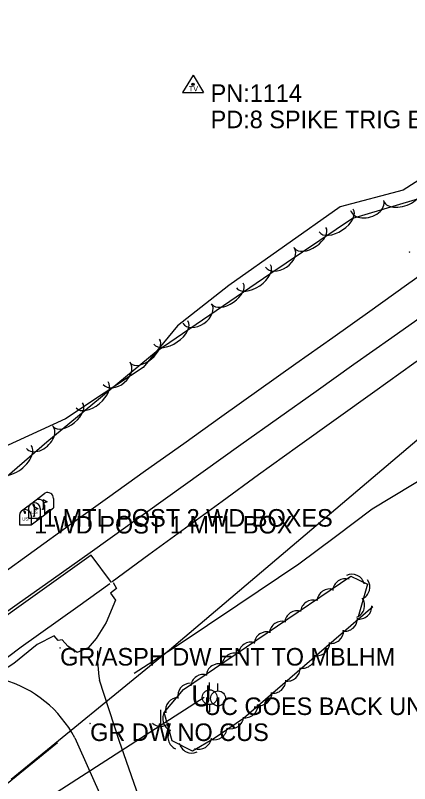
# Model space of a CAD drawing. Extents: x 1451369 to 1458940, y 1868647 to 1875095.
# Drawn here: x 1454030.9 to 1454143.2, y 1871239.9 to 1871458.6 of the extents above; entities that cross this region are included whole.
import ezdxf

# ---------------------------------------------------------------- set-up
doc = ezdxf.new("R2010")
doc.units = 0
for name, color, linetype in [('Default', 7, 'Continuous'), ('E_Const Align', 7, 'Continuous'), ('E_No Plot', 7, 'Continuous'), ('E_Proposed ROW and Easements', 7, 'Continuous'), ('E_Proposed ROW Fig Annot', 7, 'Continuous'), ('E_Quarter Section Line', 7, 'Continuous'), ('E_ROW Point Number', 7, 'Continuous'), ('E_Station Offset', 7, 'Continuous'), ('E_Survey Point Number', 7, 'Continuous'), ('S_EDGE_PAVEMENT', 7, 'Continuous'), ('S_EXIST_ROW', 7, 'Continuous'), ('S_MAILBOX_ANNOT', 7, 'Continuous'), ('S_PARKING', 7, 'Continuous'), ('S_PAVEMENT_CROWN', 7, 'Continuous'), ('S_SECONDARY_CTL_ANNOT', 7, 'Continuous'), ('S_SURVEY_TEXT_ANNOT', 7, 'Continuous'), ('S_UNDERGROUND_CABLE_ANNOT', 7, 'Continuous')]:
    doc.layers.add(name, color=color, linetype=linetype)

msp = doc.modelspace()

# ---------------------------------------------------------------- linework, layer by layer
at = {"layer": 'E_Const Align'}
for p, q in [((1454086.22, 1871266.55), (1454086.22, 1871268.68)), ((1454088.52, 1871266.28), (1454088.52, 1871268.39)), ((1454086.22, 1871262.33), (1454086.22, 1871260.27)), ((1454072.23, 1871260.88), (1454072.23, 1871256.16))]:
    msp.add_line(p, q, dxfattribs=at)
for centre, radius in [((1454086.24, 1871264.47), 2.11), ((1454088.64, 1871264.14), 2.13)]:
    msp.add_circle(centre, radius, dxfattribs=at)
msp.add_arc((1454072.29, 1871259.58), 3.41, 226.3972, 313.6028, dxfattribs=at)
at = {"layer": 'E_No Plot'}
msp.add_lwpolyline([(1454074.79, 1871277.88), (1454074.79, 1871277.93), (1454074.79, 1871277.88), (1454074.74, 1871277.88), (1454074.79, 1871277.88), (1454074.79, 1871277.83), (1454074.79, 1871277.88), (1454074.84, 1871277.88)], dxfattribs=at)
at = {"layer": 'E_Proposed ROW and Easements'}
for points in [[(1454143.12, 1871391.19), (1454143.12, 1871391.24), (1454143.12, 1871391.19), (1454143.07, 1871391.19), (1454143.12, 1871391.19), (1454143.12, 1871391.14), (1454143.12, 1871391.19), (1454143.17, 1871391.19)], [(1454043.64, 1871278.49), (1454043.64, 1871278.54), (1454043.64, 1871278.49), (1454043.59, 1871278.49), (1454043.64, 1871278.49), (1454043.64, 1871278.44), (1454043.64, 1871278.49), (1454043.69, 1871278.49)], [(1454052.19, 1871257.01), (1454052.19, 1871257.06), (1454052.19, 1871257.01), (1454052.14, 1871257.01), (1454052.19, 1871257.01), (1454052.19, 1871256.96), (1454052.19, 1871257.01), (1454052.24, 1871257.01)]]:
    msp.add_lwpolyline(points, dxfattribs=at)
at = {"layer": 'E_Proposed ROW Fig Annot'}
for p, q in [((1454035.18, 1871319.47), (1454039.32, 1871322.58)), ((1454041.75, 1871321.1), (1454041.75, 1871318.39)), ((1454032.62, 1871317.51), (1454036.76, 1871320.62)), ((1454036.24, 1871318.8), (1454036.24, 1871316.09)), ((1454038.8, 1871320.76), (1454038.8, 1871318.04)), ((1454039.19, 1871319.15), (1454039.19, 1871316.43)), ((1454034.63, 1871318.19), (1454034.63, 1871315.48)), ((1454037.96, 1871315.48), (1454041.75, 1871318.39)), ((1454037.96, 1871318.19), (1454037.96, 1871315.48)), ((1454032.07, 1871316.24), (1454032.07, 1871313.52)), ((1454034.63, 1871315.48), (1454037.96, 1871315.48)), ((1454035.39, 1871313.52), (1454039.19, 1871316.43)), ((1454035.39, 1871316.24), (1454035.39, 1871313.52)), ((1454032.07, 1871313.52), (1454035.39, 1871313.52))]:
    msp.add_line(p, q, dxfattribs=at)
for points in [[(1454035.82, 1871319.31), (1454036.04, 1871319.17), (1454036.04, 1871318.78), (1454036.34, 1871318.78), (1454036.34, 1871319.14), (1454036.15, 1871319.39), (1454035.82, 1871319.34)], [(1454036.24, 1871318.8), (1454037.35, 1871318.14), (1454036.24, 1871317.79)], [(1454038.8, 1871320.76), (1454039.91, 1871320.09), (1454038.8, 1871319.75)], [(1454033.25, 1871317.35), (1454033.47, 1871317.22), (1454033.47, 1871316.83), (1454033.78, 1871316.83), (1454033.78, 1871317.19), (1454033.59, 1871317.44), (1454033.25, 1871317.38)]]:
    msp.add_lwpolyline(points, dxfattribs=at)
for centre, end in [((1454040.09, 1871321.1), 117.5718), ((1454036.29, 1871318.19), 180), ((1454037.53, 1871319.15), 117.5718), ((1454033.73, 1871316.24), 180)]:
    msp.add_arc(centre, 1.66, 0, end, dxfattribs=at)
for centre in [(1454038.8, 1871318.04), (1454036.24, 1871316.09)]:
    msp.add_ellipse(centre, major_axis=(0.145, 0.132), ratio=0.564646, dxfattribs=at)
at = {"layer": 'E_Quarter Section Line'}
for p, q in [((1454214.32, 1871396.25), (1454074.79, 1871277.88)), ((1454074.79, 1871277.88), (1454029.66, 1871241.04))]:
    msp.add_line(p, q, dxfattribs=at)
at = {"layer": 'E_ROW Point Number'}
for points in [[(1454225.87, 1871461.79), (1454192.81, 1871439.12), (1454167.71, 1871418.57), (1454152.7, 1871408.42), (1454126.89, 1871400.74), (1454103.34, 1871384.91), (1454070.96, 1871362.85), (1454039.82, 1871337.12), (1453992.45, 1871296.2)], [(1454132.67, 1871290.19), (1454095.85, 1871258.38), (1454087.55, 1871252.77), (1454081.39, 1871249.11), (1454075.55, 1871252.05), (1454073.28, 1871260.08), (1454078.77, 1871266.7), (1454126.42, 1871298.91), (1454131.19, 1871296.67), (1454128.55, 1871287.33)]]:
    msp.add_lwpolyline(points, dxfattribs=at)
for centre, major_axis, ratio, start_param, end_param in [((1454141.03, 1871407.16), (5.11, 1.52), 0.542113, 3.141907, 6.2835), ((1454131.11, 1871404.48), (4.74, 1.41), 0.687103, 3.142126, 6.283719), ((1454122.28, 1871400.2), (4.87, 3.27), 0.550075, 3.141593, 6.283185), ((1454114.92, 1871395.25), (4.44, 2.98), 0.540695, 3.141593, 6.283185), ((1454106.22, 1871389.72), (4.11, 2.76), 0.685305, 3.141593, 6.283185), ((1454098.69, 1871384.31), (4.85, 3.3), 0.550075, 3.141593, 6.283185), ((1454091.36, 1871379.32), (4.42, 3.01), 0.540695, 3.141593, 6.283185), ((1454082.7, 1871373.73), (4.1, 2.79), 0.685305, 3.141593, 6.283185), ((1454075.19, 1871368.3), (4.85, 3.3), 0.550075, 3.141593, 6.283185), ((1454067.83, 1871363.02), (4.12, 3.41), 0.540696, 3.141593, 6.283185), ((1454059.73, 1871356.66), (3.82, 3.16), 0.685306, 3.141593, 6.283185), ((1454052.76, 1871350.56), (4.52, 3.74), 0.550076, 3.141593, 6.283185), ((1454045.92, 1871344.91), (4.12, 3.41), 0.540696, 3.141593, 6.283185), ((1454037.78, 1871338.51), (3.75, 3.24), 0.685331, 3.141629, 6.283222), ((1454030.95, 1871332.26), (4.44, 3.84), 0.550096, 3.141615, 6.283208), ((1454126.74, 1871295.83), (-3.3, 1.55), 0.999916, 3.825789, 5.598989), ((1454124.9, 1871294.58), (-1.86, -3.13), 0.999975, 3.385404, 5.158604), ((1454128.23, 1871295.83), (-3.32, 1.49), 0.993074, 2.400516, 4.173717), ((1454120.44, 1871291.66), (-1.86, -3.13), 0.999975, 3.385404, 5.158604), ((1454126.75, 1871290.63), (-3.32, 1.49), 0.993074, 2.400516, 4.173717), ((1454115.75, 1871288.52), (-1.86, -3.13), 0.999975, 3.385404, 5.158605), ((1454128.79, 1871290.36), (-1.23, 3.43), 0.999719, 2.624497, 4.397697), ((1454111.24, 1871285.48), (-1.86, -3.13), 0.999975, 3.385404, 5.158605), ((1454106.86, 1871282.47), (-1.86, -3.13), 0.999975, 3.385404, 5.158604), ((1454124.71, 1871286.92), (-1.23, 3.43), 0.999719, 2.624497, 4.397697), ((1454102.53, 1871279.46), (-1.86, -3.13), 0.999975, 3.385404, 5.158604), ((1454120.76, 1871283.42), (-1.23, 3.43), 0.999719, 2.624497, 4.397697), ((1454098.07, 1871276.53), (-1.86, -3.13), 0.999975, 3.385404, 5.158604), ((1454116.77, 1871279.92), (-1.23, 3.43), 0.999719, 2.624497, 4.397697), ((1454093.37, 1871273.39), (-1.86, -3.13), 0.999975, 3.385404, 5.158605), ((1454112.65, 1871276.37), (-1.23, 3.43), 0.999719, 2.624497, 4.397697), ((1454088.86, 1871270.35), (-1.86, -3.13), 0.999975, 3.385404, 5.158605), ((1454084.49, 1871267.35), (-1.86, -3.13), 0.999975, 3.385404, 5.158604), ((1454108.36, 1871272.7), (-1.23, 3.43), 0.999719, 2.624497, 4.397697), ((1454104.28, 1871269.27), (-1.23, 3.43), 0.999719, 2.624497, 4.397697), ((1454080.76, 1871264.81), (2.49, -2.66), 0.995904, 2.381358, 4.154559), ((1454077.31, 1871260.76), (2.49, -2.66), 0.995904, 2.381358, 4.154559), ((1454100.33, 1871265.76), (-1.23, 3.43), 0.999719, 2.624497, 4.397697), ((1454096.34, 1871262.27), (-1.23, 3.43), 0.999719, 2.624497, 4.397697), ((1454076.5, 1871258.36), (-0.4, -3.62), 0.999768, 4.212067, 5.985268), ((1454092.28, 1871259.14), (3.02, 2.04), 0.99998, 3.825789, 5.598989), ((1454087.59, 1871256.01), (3.02, 2.04), 0.99998, 3.825789, 5.598989), ((1454077.98, 1871253.12), (-0.4, -3.62), 0.999768, 4.212067, 5.985268), ((1454081.15, 1871252.21), (2.54, -2.61), 0.9999, 4.157531, 5.930732), ((1454083.15, 1871253.34), (-0.9, 3.53), 0.999827, 2.541953, 4.315153)]:
    msp.add_ellipse(centre, major_axis=major_axis, ratio=ratio, start_param=start_param, end_param=end_param, dxfattribs=at)
at = {"layer": 'E_Station Offset'}
for p, q in [((1454081.5, 1871441.59), (1454078.49, 1871436.63)), ((1454081.5, 1871441.59), (1454084.45, 1871436.63)), ((1454078.49, 1871436.63), (1454084.45, 1871436.63))]:
    msp.add_line(p, q, dxfattribs=at)
for radius in [0.311, 0.183, 0.103]:
    msp.add_circle((1454081.5, 1871438.98), radius, dxfattribs=at)
at = {"layer": 'E_Survey Point Number'}
msp.add_line((1454084.63, 1871264.41), (1454036.46, 1871233.42), dxfattribs=at)
at = {"layer": 'S_EDGE_PAVEMENT'}
for points in [[(1454173.72, 1871404.14), (1454163.25, 1871396.68), (1454152.79, 1871389.23), (1454142.32, 1871381.77), (1454131.86, 1871374.32), (1454121.32, 1871366.84), (1454110.78, 1871359.35), (1454100.24, 1871351.87), (1454089.7, 1871344.39), (1454078.83, 1871336.64), (1454067.96, 1871328.89), (1454057.09, 1871321.14), (1454046.23, 1871313.39), (1454026.17, 1871298.9), (1454006.11, 1871284.4), (1453989.42, 1871272.42), (1453978.82, 1871264.94), (1453968.21, 1871257.46), (1453957.61, 1871249.98), (1453947.01, 1871242.51), (1453929.87, 1871230.39)], [(1454185.01, 1871388.14), (1454177.7, 1871382.57), (1454160.58, 1871370.75), (1454144.37, 1871359.47), (1454133.32, 1871351.56), (1454122.27, 1871343.65), (1454111.22, 1871335.74), (1454100.17, 1871327.83), (1454089.75, 1871320.21), (1454079.33, 1871312.59), (1454068.91, 1871304.97), (1454058.49, 1871297.35)], [(1454058.27, 1871297.14), (1454052.51, 1871304.9), (1454032.56, 1871290.65), (1454020.68, 1871282.23), (1454008.81, 1871273.8), (1454000.36, 1871267.57), (1453995.51, 1871263.87), (1453998.91, 1871258.87), (1454001.34, 1871255.84), (1454014.47, 1871265.24), (1454032.57, 1871278.79), (1454048.7, 1871290.33), (1454057.83, 1871296.85)], [(1454058.72, 1871297.11), (1454059.72, 1871295.46), (1454057.98, 1871294.09), (1454059.4, 1871292.13), (1454056.72, 1871285.74), (1454053.94, 1871281.16), (1454051.62, 1871278.54), (1454048.45, 1871277.23), (1454045.82, 1871279.05), (1454044.18, 1871280.81), (1454043.08, 1871280.66), (1454041.95, 1871282), (1454037.07, 1871279.5), (1454030.44, 1871274.03), (1454025.53, 1871270.97), (1454020.65, 1871267.99), (1454016.09, 1871265.75)]]:
    msp.add_lwpolyline(points, dxfattribs=at)
at = {"layer": 'S_EXIST_ROW'}
for points in [[(1454165.41, 1871421.39), (1454158.98, 1871420.15), (1454141.36, 1871408.85), (1454123.38, 1871404.07), (1454107.55, 1871392.87), (1454091.72, 1871381.67), (1454077.11, 1871370.25), (1454067.26, 1871358.33), (1454056.22, 1871351.03), (1454045.19, 1871343.73), (1454027.6, 1871335.62)], [(1454064.7, 1871271.29), (1454076.94, 1871279.19), (1454094.28, 1871290.8), (1454111.61, 1871302.41), (1454122.07, 1871310.24), (1454132.53, 1871318.08), (1454149.99, 1871328.61), (1454167.45, 1871339.14), (1454179.62, 1871344.24)], [(1454042.87, 1871251.45), (1454027.01, 1871238.63)]]:
    msp.add_lwpolyline(points, dxfattribs=at)
at = {"layer": 'S_PARKING'}
for points in [[(1454106.8, 1871068), (1454094.84, 1871117.33), (1454089.1, 1871154.74), (1454083.76, 1871181.06), (1454071.7, 1871220.04), (1454060.42, 1871252.14), (1454054.87, 1871269.35)], [(1454047.83, 1871252.9), (1454059.9, 1871225.83)]]:
    msp.add_lwpolyline(points, dxfattribs=at)
for centre, major_axis, ratio, start_param, end_param in [((1454091.76, 1871277.55), (-17.48, -34.67), 0.956561, 5.159484, 5.376742), ((1454018.86, 1871237.67), (-17.15, 28.44), 0.985488, 4.654519, 5.470219)]:
    msp.add_ellipse(centre, major_axis=major_axis, ratio=ratio, start_param=start_param, end_param=end_param, dxfattribs=at)
at = {"layer": 'S_PAVEMENT_CROWN'}
msp.add_lwpolyline([(1454179.61, 1871396.18), (1454169.23, 1871388.84), (1454158.84, 1871381.49), (1454148.46, 1871374.14), (1454138.08, 1871366.8), (1454127.34, 1871359.17), (1454116.6, 1871351.55), (1454105.86, 1871343.93), (1454095.11, 1871336.3), (1454084.38, 1871328.63), (1454073.65, 1871320.95), (1454062.91, 1871313.27), (1454052.18, 1871305.6), (1454041.79, 1871298.22), (1454031.39, 1871290.85), (1454021, 1871283.47), (1454010.6, 1871276.1), (1453994.45, 1871264.5), (1453984.08, 1871257.16), (1453973.71, 1871249.81), (1453963.34, 1871242.47), (1453952.97, 1871235.12), (1453935.67, 1871223.29)], dxfattribs=at)

# ---------------------------------------------------------------- texts
at = {"layer": 'Default'}
msp.add_text('U', height=6, rotation=360, dxfattribs=at).set_placement((1454081, 1871261.87))
at = {"layer": 'E_Proposed ROW Fig Annot'}
for p in [(1454035.39, 1871316.67), (1454032.83, 1871314.72)]:
    msp.add_text('US', height=0.96, rotation=360, dxfattribs=at).set_placement(p)
at = {"layer": 'E_Station Offset'}
msp.add_text('TV', height=1.5, rotation=360, dxfattribs=at).set_placement((1454080.3, 1871436.97))
at = {"layer": 'S_MAILBOX_ANNOT'}
for s, p in [('1 MTL POST 2 WD BOXES', (1454038.8, 1871313.04)), ('1 WD POST 1 MTL BOX', (1454036.24, 1871311.09))]:
    msp.add_text(s, height=5, dxfattribs=at).set_placement(p)
at = {"layer": 'S_SECONDARY_CTL_ANNOT'}
for s, p in [('PN:1114', (1454086.5, 1871433.98)), ('PD:8 SPIKE TRIG ELEV', (1454086.5, 1871426.48))]:
    msp.add_text(s, height=5, dxfattribs=at).set_placement(p)
at = {"layer": 'S_SURVEY_TEXT_ANNOT'}
for s, p in [('GR/ASPH DW ENT TO MBLHM', (1454043.64, 1871273.49)), ('GR DW NO CUS', (1454052.19, 1871252.01))]:
    msp.add_text(s, height=5, dxfattribs=at).set_placement(p)
at = {"layer": 'S_UNDERGROUND_CABLE_ANNOT'}
msp.add_text('UC GOES BACK UNDERGROUND', height=5, dxfattribs=at).set_placement((1454084.63, 1871259.41))

doc.saveas('drawing.dxf')
